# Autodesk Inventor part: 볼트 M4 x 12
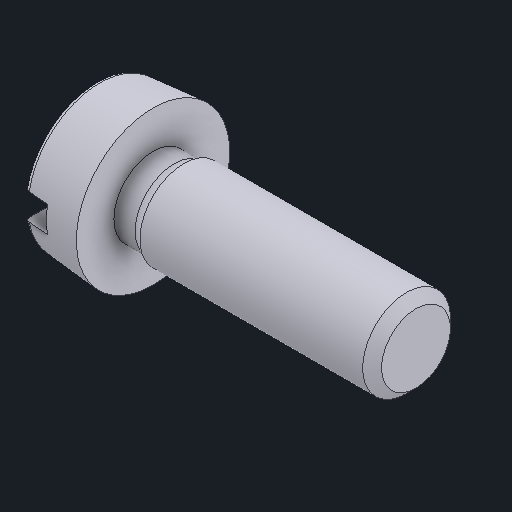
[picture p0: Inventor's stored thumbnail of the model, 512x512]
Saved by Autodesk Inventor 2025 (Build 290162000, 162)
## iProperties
Created: 2025-08
Part Number: 볼트 M4 x 12
Material: 강철, 연강
Description: 6각머리 태핑 나사
Document SubType Name: Modeling
Designer: infra11
Density: 7.85 g/cm^3
Appearance: 기본값
Author: jhkim
Sending System: Autodesk Inventor 2026
Preprocessor: ST-DEVELOPER v20.1
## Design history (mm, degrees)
feature "Solid1"
node "솔리드1"
